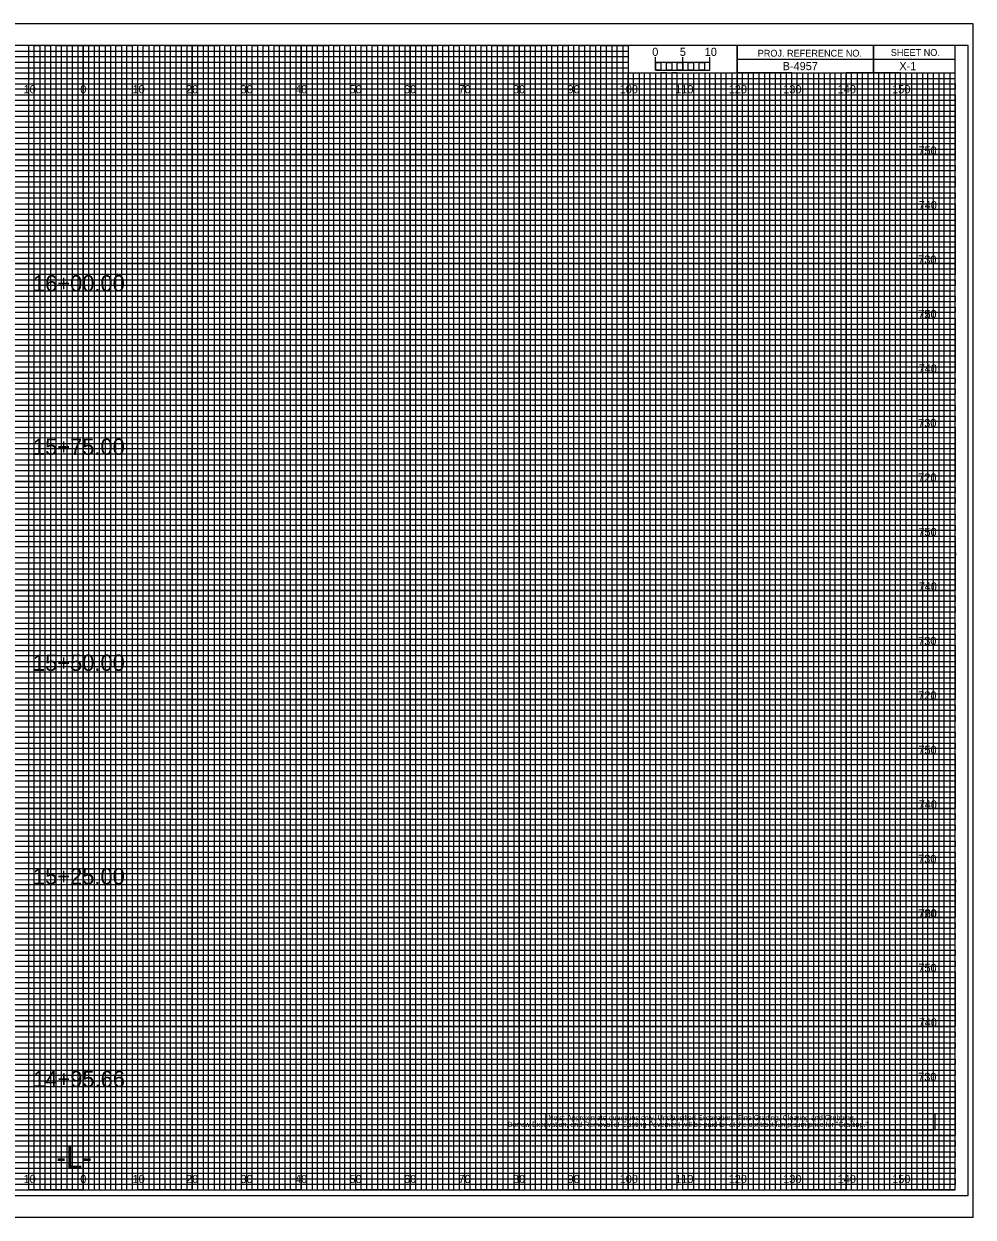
# Model space of a CAD drawing. Extents: x -13 to 323, y -5 to 214.
# Drawn here: x 149.1 to 323.3, y -5 to 214 of the extents above; entities that cross this region are included whole.
import ezdxf

# ---------------------------------------------------------------- set-up
doc = ezdxf.new("R2010")
doc.units = 0
for name, color, linetype in [('Prop Grid Mask', 7, 'Continuous'), ('Prop XS Alignment Label', 7, 'Continuous'), ('Prop XS Bar Scale Labels', 7, 'Continuous'), ('Prop XS Elevation Labels', 7, 'Continuous'), ('Prop XS Offset Labels', 7, 'Continuous'), ('Prop XS Project Number', 7, 'Continuous'), ('Prop XS Sheet Number', 7, 'Continuous'), ('Prop XS Station Labels', 7, 'Continuous'), ('Prop XSC Text', 7, 'Continuous'), ('Sheet Cross Section CELL', 7, 'Continuous'), ('Sheet Cross Section Grid Major CELL', 7, 'Continuous'), ('Sheet Cross Section Grid Middle CELL', 7, 'Continuous'), ('Sheet Cross Section Grid Minor 1 CELL', 7, 'Continuous'), ('Sheet Cross Section Grid Minor 2 CELL', 7, 'Continuous'), ('Sheet Cross Section Scale CELL', 7, 'Continuous'), ('Sheet Cutting Line CELL', 7, 'Continuous'), ('Sheet DOT Grid CELL', 7, 'Continuous'), ('Sheet Plot Border Inside CELL', 7, 'Continuous'), ('Sheet Plot Border Outside CELL', 7, 'Continuous')]:
    doc.layers.add(name, color=color, linetype=linetype)

msp = doc.modelspace()

# ---------------------------------------------------------------- linework, layer by layer
at = {"layer": 'Prop Grid Mask'}
msp.add_lwpolyline([(244.92, 14.01), (316.29, 14.01), (316.29, 10.98), (244.92, 10.98)], close=True, dxfattribs=at)
at = {"layer": 'Sheet Cross Section CELL'}
for p, q in [((305, 210), (305, 205)), ((305, 205), (305, 210)), ((280, 207.5), (280, 205)), ((320, 207.49), (280, 207.49)), ((280, 205), (320, 205))]:
    msp.add_line(p, q, dxfattribs=at)
for points in [[(320, 210), (0, 210), (0, 0), (320, 0)], [(280, 210), (260, 210), (260, 205.03), (280, 205.03)], [(320, 210), (280, 210), (280, 205), (320, 205)]]:
    msp.add_lwpolyline(points, close=True, dxfattribs=at)
at = {"layer": 'Sheet Cross Section Grid Major CELL'}
for p, q in [((150, 210), (140, 210)), ((150, 0), (150, 210)), ((170, 210), (160, 210)), ((160, 210), (160, 0)), ((170, 0), (170, 210)), ((190, 210), (180, 210)), ((180, 210), (180, 0)), ((190, 0), (190, 210)), ((210, 210), (200, 210)), ((200, 210), (200, 0)), ((210, 0), (210, 210)), ((230, 210), (220, 210)), ((220, 210), (220, 0)), ((230, 0), (230, 210)), ((250, 210), (240, 210)), ((240, 210), (240, 0)), ((250, 0), (250, 210)), ((260, 210), (260, 0)), ((270, 0), (270, 205)), ((290, 205), (280, 205)), ((280, 205), (280, 0)), ((290, 0), (290, 205)), ((310, 205), (300, 205)), ((300, 205), (300, 0)), ((310, 0), (310, 205)), ((160, 0), (150, 0)), ((180, 0), (170, 0)), ((200, 0), (190, 0)), ((220, 0), (210, 0)), ((240, 0), (230, 0)), ((260, 0), (250, 0)), ((280, 0), (270, 0)), ((300, 0), (290, 0)), ((320, 0), (310, 0)), ((320, 0), (320, 0))]:
    msp.add_line(p, q, dxfattribs=at)
for points in [[(0, 200), (320, 200), (320, 190), (0, 190)], [(0, 180), (320, 180), (320, 170), (0, 170)], [(0, 160), (320, 160), (320, 150), (0, 150)], [(0, 140), (320, 140), (320, 130), (0, 130)], [(0, 120), (320, 120), (320, 110), (0, 110)], [(0, 100), (320, 100), (320, 90), (0, 90)], [(0, 80), (320, 80), (320, 70), (0, 70)], [(0, 60), (320, 60), (320, 50), (0, 50)], [(0, 40), (320, 40), (320, 30), (0, 30)], [(0, 20), (320, 20), (320, 10), (0, 10)]]:
    msp.add_lwpolyline(points, dxfattribs=at)
at = {"layer": 'Sheet Cross Section Grid Middle CELL'}
for points in [[(145, 0), (155, 0), (155, 210), (165, 210), (165, 0), (175, 0), (175, 210), (185, 210), (185, 0), (195, 0), (195, 210), (205, 210), (205, 0), (215, 0), (215, 210), (225, 210), (225, 0), (235, 0), (235, 210), (245, 210), (245, 0), (255, 0), (255, 210), (259.93, 210), (260, 210), (260, 205), (264.99, 205), (264.99, 0), (275, 0), (275, 205), (285, 205), (285, 0), (295, 0), (295, 205), (305, 205), (305, 0), (315, 0), (315, 205)], [(0, 205), (275, 205)], [(0, 185), (320, 185), (320, 195), (0, 195)], [(0, 165), (320, 165), (320, 175), (0, 175)], [(0, 145), (320, 145), (320, 155), (0, 155)], [(0, 125), (320, 125), (320, 135), (0, 135)], [(0, 105), (320, 105), (320, 115), (0, 115)], [(0, 85), (320, 85), (320, 95), (0, 95)], [(0, 65), (320, 65), (320, 75), (0, 75)], [(0, 45), (320, 45), (320, 55), (0, 55)], [(0, 25), (320, 25), (320, 35), (0, 35)], [(0, 5), (320, 5), (320, 15), (0, 15)]]:
    msp.add_lwpolyline(points, dxfattribs=at)
at = {"layer": 'Sheet Cross Section Grid Minor 1 CELL'}
for p, q in [((0, 209), (260, 209)), ((260, 209), (260, 207.98)), ((260, 207.98), (0, 207.98)), ((0, 207), (260, 207)), ((260, 205.89), (0, 205.89)), ((260, 207), (260, 205.89)), ((0, 204), (320, 204))]:
    msp.add_line(p, q, dxfattribs=at)
for points in [[(0, 203), (270, 203), (320, 203), (320, 202), (0, 202)], [(0, 201), (320, 201), (320, 199), (0, 199)], [(0, 198), (320, 198), (320, 197), (0, 196.98)], [(0, 196), (320, 196), (320, 194), (0, 194)], [(0, 193), (320, 193), (320, 192), (0, 192)], [(0, 191), (320, 191), (320, 189), (0, 189)], [(0, 188), (320, 188), (320, 187), (0, 187)], [(0, 186), (320, 186), (320, 184), (0, 184)], [(0, 183), (320, 183), (320, 182), (0, 182)], [(0, 181), (320, 181), (320, 179), (0, 179)], [(0, 178), (320, 178), (320, 177), (0, 177)], [(0, 176), (320, 176), (320, 173.95), (320, 173), (320, 172), (0, 172)], [(0, 174), (320, 174), (320, 173), (0, 173)], [(0, 171), (320, 171), (320, 169), (0, 169.03)], [(0, 169.03), (320, 169), (320, 168), (0, 168)], [(0, 167), (320, 167), (320, 166), (0, 166)], [(0, 164), (320, 164), (320, 163), (0, 163)], [(0, 162), (320, 162), (320, 161), (0, 161)], [(-0.07, 158.89), (320, 158.89), (320, 157.88), (-0.07, 157.88)], [(0, 157), (320, 157), (320, 156), (0, 156)], [(0, 154), (320, 154), (320, 153), (0, 153)], [(0, 152), (320, 152), (320, 151), (0, 151)], [(0, 149), (320, 149), (320, 148), (0, 148)], [(0, 147), (320, 147), (320, 146), (0, 146)], [(0, 144), (320, 144), (320, 143), (0, 143)], [(0, 142), (320, 142), (320, 141), (0, 141)], [(0, 139), (320, 139), (319.99, 137.98), (0, 138)], [(0, 137), (320, 137), (320, 136), (0, 136)], [(0, 134), (320, 134), (320, 133), (0, 133)], [(0, 132), (320, 132), (320, 131), (0, 131)], [(0, 129), (320, 129), (320, 128), (0, 128)], [(0, 127), (320, 127), (320, 126), (0, 126)], [(0, 124), (320, 124), (320, 123), (0, 123)], [(0, 122), (320, 122), (320, 121), (0, 121)], [(0, 119), (320, 119), (320, 118), (0, 118)], [(0, 116.99), (320.07, 116.91), (320, 116), (0, 116)], [(0, 114), (320, 114), (320, 113), (0, 113)], [(0, 112), (320, 112), (320, 111), (0, 111)], [(0, 109), (320, 109), (320, 108), (0, 108)], [(0, 107), (320, 107), (320, 106), (0, 106)], [(0, 104), (320, 104), (320, 103), (0, 103)], [(0, 102), (320, 102), (320, 101), (0, 101)], [(0, 99), (320, 99), (320, 98), (0, 98)], [(0, 97), (320, 97), (320, 96), (0, 96)], [(0, 94), (320, 94), (320, 93), (0, 93)], [(0, 92), (320, 92), (320, 91), (0, 91)], [(0, 89), (320, 89), (320, 88), (0, 88)], [(0, 87), (320, 87), (320, 86), (0, 86)], [(0, 84), (320, 84), (320, 83), (0, 83)], [(0, 82), (320, 82), (320, 81), (0, 81)], [(0, 79), (320, 79), (319.99, 77.98), (0, 78)], [(0, 77), (320, 77), (320, 76), (0, 76)], [(0, 74), (320, 74), (320, 73), (0, 73)], [(0, 72), (320, 72), (320, 71), (0, 71)], [(0, 69), (320, 69), (320, 68), (0, 68)], [(0, 67), (320, 67), (320, 66), (0, 66)], [(0, 64), (320, 64), (320, 63), (0, 63)], [(0, 62), (320, 62), (320, 61), (0, 61)], [(0, 59), (320, 59), (320, 58), (0, 58)], [(0, 56.99), (320.07, 56.91), (320, 56), (0, 56)], [(0, 54), (320, 54), (320, 53), (0, 53)], [(0, 52), (320, 52), (320, 51), (0, 51)], [(0, 49), (320, 49), (320, 48), (0, 48)], [(0, 47), (320, 47), (320, 46), (0, 46)], [(0, 44), (320, 44), (320, 43), (0, 43)], [(0, 42), (320, 42), (320, 41), (0, 41)], [(0, 39), (320, 39), (320, 38), (0, 38)], [(0, 37), (320, 37), (320, 36), (0, 36)], [(0, 34), (320, 34), (320, 33), (0, 33)], [(0, 32), (320, 32), (320, 31), (0, 31)], [(0, 29), (320, 29), (320, 28), (0, 28)], [(0, 27), (320, 27), (320, 26), (0, 26)], [(0, 24), (320, 24), (320, 23), (0, 23)], [(0, 22), (320, 22), (320, 21), (0, 21)], [(0, 19), (320, 19), (320, 18), (0, 18)], [(0, 17), (320, 17), (320, 16), (0, 16)], [(0, 14), (320, 14), (320, 13), (0, 13)], [(0, 12), (320, 12), (320, 11), (0, 11)], [(0, 9), (320, 9), (320, 8), (0, 8)], [(0, 7), (320, 7), (320, 6), (0, 6)], [(0, 4), (320, 4), (320, 3), (0, 3)], [(0, 2), (320, 2), (320, 1), (0, 1)]]:
    msp.add_lwpolyline(points, dxfattribs=at)
at = {"layer": 'Sheet Cross Section Grid Minor 2 CELL'}
for p, q in [((267, 205), (266.01, 205)), ((266.01, 205), (266.01, 0)), ((267, 0), (267, 205)), ((269, 205), (268, 205)), ((268, 205), (268, 0)), ((269, 0), (269, 205)), ((266.01, 0), (265, 0)), ((268, 0), (267, 0))]:
    msp.add_line(p, q, dxfattribs=at)
for points in [[(150, 0), (151, 0), (151, 210), (152, 210), (152, 0)], [(152, 0), (153, 0), (153, 210), (154, 210), (154, 0)], [(155, 0), (156, 0), (156, 210), (157, 210), (157, 0)], [(157, 0), (158, 0), (158, 210), (159, 210), (159, 0)], [(160, 0), (161, 0), (161, 210), (162, 210), (162, 0)], [(162, 0), (163, 0), (163, 210), (164, 210), (164, 0)], [(165, 0), (166, 0), (166, 210), (167, 210), (167, 0)], [(167, 0), (168, 0), (168, 210), (169, 210), (169, 0)], [(170, 0), (171, 0), (171, 210), (172, 210), (172, 0)], [(172, 0), (173, 0), (173, 210), (174, 210), (174, 0)], [(175, 0), (176, 0), (176, 210), (177, 210), (177, 0)], [(177, 0), (178, 0), (178, 210), (179, 210), (179, 0)], [(180, 0), (181, 0), (181, 210), (182, 210), (182, 0)], [(182, 0), (183, 0), (183, 210), (184, 210), (184, 0)], [(185, 0), (186, 0), (186, 210), (187, 210), (187, 0)], [(187, 0), (188, 0), (188, 210), (189, 210), (189, 0)], [(190, 0), (191, 0), (191, 210), (192, 210), (192, 0)], [(192, 0), (193, 0), (193, 210), (194, 210), (194, 0)], [(195, 0), (196, 0), (196, 210), (197, 210), (197, 0)], [(197, 0), (198, 0), (198, 210), (199, 210), (199, 0)], [(200, 0), (201, 0), (201, 210), (202, 210), (202, 0)], [(202, 0), (203, 0), (203, 210), (204, 210), (204, 0)], [(205, 0), (206, 0), (206, 210), (207, 210), (207, 0)], [(207, 0), (208, 0), (208, 210), (209, 210), (209, 0)], [(210, 0), (211, 0), (211, 210), (212, 210), (212, 0)], [(212, 0), (213, 0), (213, 210), (214, 210), (214, 0)], [(215, 0), (216, 0), (216, 210), (217, 210), (217, 0)], [(217, 0), (218, 0), (218, 210), (219, 210), (219, 0)], [(220, 0), (221, 0), (221, 210), (222, 210), (222, 0)], [(222, 0), (223, 0), (223, 210), (224, 210), (224, 0)], [(225, 0), (226, 0), (226, 210), (227, 210), (227, 0)], [(227, 0), (228, 0), (228, 210), (229, 210), (229, 0)], [(230, 0), (231, 0), (231, 210), (232, 210), (232, 0)], [(232, 0), (233, 0), (233, 210), (234, 210), (234, 0)], [(235, 0), (236, 0), (236, 210), (237, 210), (237, 0)], [(237, 0), (238, 0), (238, 210), (239, 210), (239, 0)], [(240, 0), (241, 0), (241, 210), (242, 210), (242, 0)], [(242, 0), (243, 0), (243, 210), (244, 210), (244, 0)], [(245, 0), (246, 0), (246, 210), (247, 210), (247, 0)], [(247, 0), (248, 0), (248, 210), (249, 210), (249, 0)], [(250, 0), (251, 0), (251, 210), (252, 210), (252, 0)], [(252, 0), (253, 0), (253, 210), (254, 210), (254, 0)], [(255, 0), (256, 0), (256, 210), (257, 210), (257, 0)], [(257, 0), (258, 0), (258, 210), (259, 210), (259, 0)], [(260, 0), (261, 0), (261, 205), (262.02, 205), (262.02, 0)], [(262, 0), (263, 0), (263, 205), (263.99, 205), (263.99, 0)], [(270, 0), (270.98, 0), (270.98, 205), (272, 205), (272, 0)], [(272, 0), (273, 0), (273, 205), (274.05, 205), (274.05, 0)], [(275, 0), (276, 0), (276, 205), (277, 205), (277, 0)], [(277, 0), (278, 0), (278, 205), (279, 205), (279, 0)], [(280, 0), (281, 0), (281, 205), (282, 205), (282, 0)], [(282, 0), (283, 0), (283, 205), (284, 205), (284, 0)], [(285, 0), (286, 0), (286, 205), (287, 205), (287, 0)], [(287, 0), (288, 0), (288, 205), (289, 205), (289, 0)], [(290, 0), (291, 0), (291, 205), (292, 205), (292, 0)], [(292, 0), (293, 0), (293, 205), (294, 205), (294, 0)], [(295, 0), (296, 0), (296, 205), (297, 205), (297, 0)], [(297, 0), (298, 0), (298, 205), (299, 205), (299, 0)], [(300, 0), (301, 0), (301, 205), (302, 205), (302, 0)], [(302, 0), (303, 0), (303, 205), (304, 205), (304, 0)], [(305, 0), (306, 0), (306, 205), (307, 205), (307, 0)], [(307, 0), (308, 0), (308, 205), (309, 205), (309, 0)], [(310, 0), (311, 0), (311, 205), (312, 205), (312, 0)], [(312, 0), (313, 0), (313, 205), (314, 205), (314, 0)], [(315, 0), (316, 0), (316, 205), (317, 205), (317, 0)], [(317, 0), (318, 0), (318, 205), (319, 205), (319, 0)]]:
    msp.add_lwpolyline(points, dxfattribs=at)
at = {"layer": 'Sheet Cross Section Scale CELL'}
for p, q in [((265, 205.49), (265, 207.9)), ((265, 206.9), (265, 207.9)), ((270, 205.49), (270, 207.9)), ((275, 205.49), (275, 207.9)), ((275, 206.9), (275, 207.9))]:
    msp.add_line(p, q, dxfattribs=at)
for points in [[(275, 206.9), (265, 206.9), (265, 205.49), (275, 205.49)], [(265, 206.9), (266, 206.9), (266, 205.49), (265, 205.49)], [(267, 206.9), (268, 206.9), (268, 205.49), (267, 205.49)], [(269, 206.9), (270, 206.9), (270, 205.49), (269, 205.49)], [(271, 206.9), (272, 206.9), (272, 205.49), (271, 205.49)], [(273, 206.9), (274, 206.9), (274, 205.49), (273, 205.49)]]:
    msp.add_lwpolyline(points, close=True, dxfattribs=at)
at = {"layer": 'Sheet Cutting Line CELL'}
for p, q in [((323.3, 214), (-13.4, 214)), ((-13.4, -5), (323.3, -5))]:
    msp.add_line(p, q, dxfattribs=at)
at = {"layer": 'Sheet DOT Grid CELL'}
for p, q in [((150, 0), (150, 210)), ((160, 0), (160, 210)), ((170, 0), (170, 210)), ((180, 0), (180, 210)), ((190, 0), (190, 210)), ((200, 0), (200, 210)), ((210, 0), (210, 210)), ((220, 0), (220, 210)), ((230, 0), (230, 210)), ((240, 0), (240, 210)), ((250, 0), (250, 210)), ((260, 0), (260, 204.69)), ((270, 0), (270, 204.69)), ((280, 0), (280, 204.69)), ((290, 0), (290, 204.69)), ((300, 0), (300, 204.69)), ((310, 0), (310, 204.69)), ((0, 200), (320, 200)), ((0, 190), (320, 190)), ((0, 180), (320, 180)), ((0, 170), (320, 170)), ((0, 160), (320, 160)), ((0, 150), (320, 150)), ((0, 140), (320, 140)), ((0, 130), (320, 130)), ((0, 120), (320, 120)), ((0, 110), (320, 110)), ((0, 100), (320, 100)), ((0, 90), (320, 90)), ((0, 80), (320, 80)), ((0, 70), (320, 70)), ((0, 60), (320, 60)), ((0, 50), (320, 50)), ((0, 40), (320, 40)), ((0, 30), (320, 30)), ((0, 20), (320, 20)), ((0, 10), (320, 10))]:
    msp.add_line(p, q, dxfattribs=at)
at = {"layer": 'Sheet Plot Border Inside CELL'}
msp.add_lwpolyline([(-10.8, -1), (322.4, -1), (322.4, 210), (-10.8, 210)], close=True, dxfattribs=at)
at = {"layer": 'Sheet Plot Border Outside CELL'}
msp.add_lwpolyline([(-13.4, -5), (323.3, -5), (323.3, 214), (-13.4, 214)], close=True, dxfattribs=at)

# ---------------------------------------------------------------- texts
at = {"layer": 'Prop XS Alignment Label'}
msp.add_text('-L-', height=4, dxfattribs=at).set_placement((155.06, 4))
at = {"layer": 'Prop XS Bar Scale Labels'}
for s, p in [('5', (269.47, 208.12)), ('10', (274.04, 208.12))]:
    msp.add_text(s, height=1.5, dxfattribs=at).set_placement(p)
at = {"layer": 'Prop XS Elevation Labels'}
for s, p in [('750', (313.25, 190)), ('740', (313.3, 180)), ('730', (313.22, 170)), ('720', (313.23, 160)), ('750', (313.25, 160)), ('740', (313.3, 150)), ('730', (313.22, 140)), ('720', (313.23, 130)), ('750', (313.25, 120)), ('740', (313.3, 110)), ('730', (313.22, 100)), ('720', (313.23, 90)), ('750', (313.25, 80)), ('740', (313.3, 70)), ('730', (313.22, 60)), ('720', (313.23, 50)), ('760', (313.3, 50)), ('750', (313.25, 40)), ('740', (313.3, 30)), ('730', (313.22, 20))]:
    msp.add_text(s, height=1.5, dxfattribs=at).set_placement(p)
at = {"layer": 'Prop XS Offset Labels'}
for s, p in [('10', (149.04, 201.25)), ('0', (159.45, 201.25)), ('0', (159.45, 201.25)), ('10', (169.04, 201.25)), ('20', (178.86, 201.25)), ('30', (188.86, 201.25)), ('40', (198.86, 201.25)), ('50', (208.86, 201.25)), ('60', (218.86, 201.25)), ('70', (228.86, 201.25)), ('80', (238.86, 201.25)), ('90', (248.86, 201.25)), ('100', (258.44, 201.25)), ('110', (268.62, 201.25)), ('120', (278.44, 201.25)), ('130', (288.44, 201.25)), ('140', (298.44, 201.25)), ('150', (308.44, 201.25)), ('10', (149.04, 1.25)), ('0', (159.45, 1.25)), ('0', (159.45, 1.25)), ('10', (169.04, 1.25)), ('20', (178.86, 1.25)), ('30', (188.86, 1.25)), ('40', (198.86, 1.25)), ('50', (208.86, 1.25)), ('60', (218.86, 1.25)), ('70', (228.86, 1.25)), ('80', (238.86, 1.25)), ('90', (248.86, 1.25)), ('100', (258.44, 1.25)), ('110', (268.62, 1.25)), ('120', (278.44, 1.25)), ('130', (288.44, 1.25)), ('140', (298.44, 1.25)), ('150', (308.44, 1.25))]:
    msp.add_text(s, height=1.5, dxfattribs=at).set_placement(p)
at = {"layer": 'Prop XS Project Number'}
msp.add_text('B-4957', height=1.5, dxfattribs=at).set_placement((288.34, 205.5))
at = {"layer": 'Prop XS Sheet Number'}
msp.add_text('X-1', height=1.5, dxfattribs=at).set_placement((309.76, 205.5))
at = {"layer": 'Prop XS Station Labels'}
for s, p in [('16+00.00', (150.77, 164.89)), ('15+75.00', (150.77, 134.89)), ('15+50.00', (150.77, 95.25)), ('15+25.00', (150.77, 56.07)), ('14+95.66', (150.8, 18.85))]:
    msp.add_text(s, height=3, dxfattribs=at).set_placement(p)
at = {"layer": 'Prop XSC Text'}
for s, p in [('Note: Approximate quantities only. Unclassified Excavation,  Fine Grading, Clearing and Grubbing,', (245.33, 12.79)), ('                  Borrow Excavation, and Removal of Existing Pavement will be paid for at the contract lump sum price for "Grading."', (231.4, 11.56))]:
    msp.add_text(s, height=0.9375, dxfattribs=at).set_placement(p)
at = {"layer": 'Sheet Cross Section CELL'}
for s, p in [('PROJ. REFERENCE NO.', (283.77, 207.99)), ('SHEET NO.', (308.19, 208.12))]:
    msp.add_text(s, height=1.25, dxfattribs=at).set_placement(p)
at = {"layer": 'Sheet Cross Section Scale CELL'}
msp.add_text('0', height=1.5, dxfattribs=at).set_placement((264.41, 208.12))

doc.saveas('drawing.dxf')
